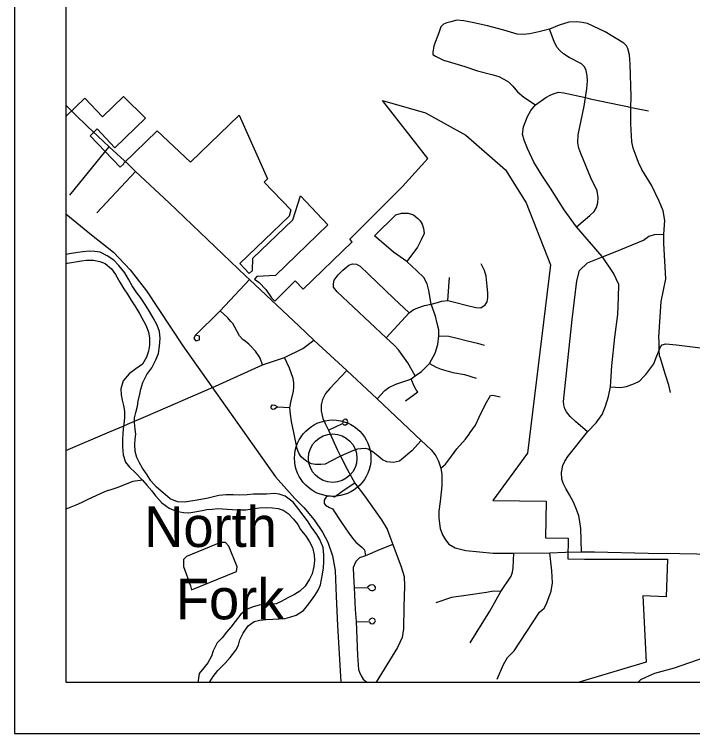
# Model space of a CAD drawing. Extents: x 0 to 34, y 0 to 22.
# Drawn here: x 2 to 3.32, y 14 to 15.4 of the extents above; entities that cross this region are included whole.
import ezdxf

# ---------------------------------------------------------------- set-up
doc = ezdxf.new("R2010")
doc.units = 0
for name, color, linetype in [('GM_X_City_Street', 7, 'Continuous'), ('GM_X_Corporation', 7, 'Continuous'), ('GM_X_County_Road', 7, 'Continuous'), ('GM_X_Major_River', 7, 'Continuous'), ('GM_X_Minor_Lake', 7, 'Continuous'), ('GM_X_Minor_River', 7, 'Continuous'), ('GM_X_Rail_Line', 7, 'Continuous'), ('GM_X_Township_Road', 7, 'Continuous'), ('GM_X_Unincorporated', 7, 'Continuous'), ('GM_X_Unincorporated_Location', 7, 'Continuous'), ('GM_X_Unincorporated_Text', 7, 'Continuous'), ('GM_X_US_Route', 7, 'Continuous'), ('SH_Data', 7, 'Continuous')]:
    doc.layers.add(name, color=color, linetype=linetype)

msp = doc.modelspace()

# ---------------------------------------------------------------- linework, layer by layer
at = {"layer": 'GM_X_City_Street'}
for points in [[(3.2773, 14.6642), (3.2737, 14.6783), (3.2666, 14.7005), (3.2573, 14.731), (3.2556, 14.7353), (3.2553, 14.7463), (3.2547, 14.7637), (3.2541, 14.7722), (3.259, 14.8414), (3.2678, 14.8853), (3.2641, 14.9544), (3.2639, 14.9723), (3.2663, 14.9988), (3.2631, 15.0178), (3.2549, 15.0368), (3.2403, 15.068), (3.2212, 15.0985), (3.2145, 15.1122), (3.2104, 15.124), (3.2041, 15.1396), (3.2019, 15.1522), (3.1999, 15.1871), (3.2001, 15.2192), (3.2003, 15.2398), (3.1984, 15.3032), (3.1974, 15.3214), (3.1937, 15.3336), (3.1915, 15.3389), (3.1862, 15.3446), (3.1501, 15.3661), (3.1153, 15.3823), (3.1051, 15.3846), (3.0949, 15.3858), (3.0794, 15.3852), (3.0604, 15.3796), (3.0418, 15.3717), (3.0206, 15.3666), (3.0031, 15.3625), (2.9906, 15.3614), (2.9789, 15.3619), (2.9524, 15.3693), (2.9207, 15.3778), (2.8942, 15.3837), (2.8749, 15.3876), (2.8609, 15.3888), (2.8492, 15.3858), (2.842, 15.384), (2.8351, 15.381), (2.8298, 15.3761), (2.8259, 15.3643), (2.8166, 15.3394), (2.8143, 15.3261), (2.8146, 15.322), (2.8195, 15.3189)], [(3.0939, 14.9866), (3.1202, 15.0085), (3.1286, 15.0164), (3.1332, 15.0243), (3.1356, 15.0334), (3.1364, 15.044), (3.1342, 15.0569), (3.1223, 15.0821), (3.1025, 15.1296), (3.0985, 15.1399), (3.0966, 15.1501), (3.0975, 15.1661), (3.1093, 15.2218), (3.1116, 15.2382), (3.114, 15.2552), (3.1153, 15.2707), (3.115, 15.281), (3.1132, 15.2912), (3.1098, 15.2981), (3.1038, 15.3038), (3.0796, 15.3161), (3.0691, 15.3234), (3.0623, 15.3291), (3.0556, 15.3364), (3.0503, 15.3478), (3.0418, 15.3717)], [(2.8195, 15.3189), (2.835, 15.3115), (2.8509, 15.3065), (2.8766, 15.2988), (2.9015, 15.2906), (2.9295, 15.2833), (2.9427, 15.2794), (2.9529, 15.2744), (2.9619, 15.269), (2.9702, 15.2606), (2.9792, 15.2495), (2.9916, 15.2392), (3.0146, 15.2243)], [(3.1154, 14.5876), (3.1325, 14.605), (3.144, 14.6215), (3.1508, 14.6374), (3.1565, 14.6561), (3.1601, 14.675), (3.1631, 14.7158), (3.1684, 14.7722), (3.1743, 14.816), (3.1756, 14.8494), (3.1762, 14.8742), (3.1658, 14.8965), (3.1447, 14.9285), (3.1442, 14.9292), (3.0939, 14.9866), (3.07, 15.0198), (3.0434, 15.0621), (3.0269, 15.0876), (3.0112, 15.1127), (2.9985, 15.139), (2.9922, 15.1554), (2.9892, 15.1668), (2.9912, 15.1812), (2.9989, 15.2012), (3.0051, 15.213), (3.0146, 15.2243), (3.0344, 15.2382), (3.0443, 15.2438), (3.0523, 15.2472), (3.0595, 15.2487), (3.0697, 15.2475), (3.1116, 15.2382), (3.1207, 15.2361), (3.1805, 15.2236), (3.1931, 15.2208), (3.2001, 15.2192), (3.2047, 15.2182), (3.2342, 15.2127)], [(3.1154, 14.5876), (3.0924, 14.6075), (3.0818, 14.6175), (3.0744, 14.6262), (3.0714, 14.6323), (3.0695, 14.6404), (3.0691, 14.6466), (3.0859, 14.8066), (3.0945, 14.8814), (3.0997, 14.9017), (3.1154, 14.9168), (3.1447, 14.9285), (3.1693, 14.9383), (3.2248, 14.9607), (3.2351, 14.9683), (3.2468, 14.972), (3.2639, 14.9723)], [(3.1601, 14.675), (3.1799, 14.6742), (3.1913, 14.6759), (3.207, 14.6818), (3.2164, 14.6865), (3.2253, 14.6956), (3.2289, 14.6992), (3.2446, 14.7201), (3.2492, 14.7322), (3.2553, 14.7463), (3.2573, 14.7529), (3.2609, 14.7571), (3.2681, 14.7587), (3.2887, 14.7568), (3.3352, 14.7509)], [(3.2141, 14.1), (3.2194, 14.1051), (3.2293, 14.1099), (3.2464, 14.1174), (3.2851, 14.1278), (3.3427, 14.148), (3.3855, 14.1619), (3.4026, 14.1648), (3.4161, 14.1631), (3.4242, 14.1411)]]:
    msp.add_lwpolyline(points, dxfattribs=at)
at = {"layer": 'GM_X_Corporation'}
for p, q in [((2.1, 15.8164), (2.1, 14.1)), ((2.1, 15.6286), (2.1, 14.9868)), ((2.1, 14.1), (7.1768, 14.1)), ((3.1961, 14.1), (6.9084, 14.1))]:
    msp.add_line(p, q, dxfattribs=at)
for points in [[(3.3801, 16.588), (3.1836, 16.4951), (3.1819, 16.4943), (3.1648, 16.4862), (3.1598, 16.4838), (3.1538, 16.4811), (2.5106, 16.1869), (2.5081, 16.1858), (2.1, 15.9991), (2.1, 14.1), (7.2283, 14.1)], [(2.1, 15.8606), (2.1, 15.2015), (2.1371, 15.2373), (2.1712, 15.2007), (2.2126, 15.2407), (2.2553, 15.1982), (2.1955, 15.1405), (2.1612, 15.1772), (2.1474, 15.1638), (2.206, 15.103), (2.2127, 15.1095), (2.2122, 15.11), (2.2781, 15.1737), (2.343, 15.1129), (2.4376, 15.2042), (2.4928, 15.0801), (2.4864, 15.0737), (2.5382, 15.02), (2.5346, 15.0075), (2.4391, 14.9152), (2.4571, 14.896), (2.4632, 14.9019), (2.4644, 14.9255), (2.5421, 15.0005), (2.5572, 15.047), (2.61, 14.9904), (2.508, 14.8918), (2.472, 14.8899), (2.4671, 14.885), (2.4767, 14.8782), (2.4896, 14.8644), (2.5006, 14.8487), (2.507, 14.842), (2.5467, 14.8817), (2.5622, 14.8656), (2.6576, 14.9577), (2.653, 14.9625), (2.7557, 15.0652), (2.805, 15.1199), (2.7168, 15.2328), (2.7999, 15.2087), (2.8789, 15.1649), (2.9559, 15.098), (2.996, 15.0332), (3.0432, 14.9125), (2.9984, 14.5461), (2.9311, 14.4538), (3.0349, 14.4525), (3.034, 14.3811), (3.078, 14.3806), (3.0775, 14.3403), (3.1099, 14.3395), (3.271, 14.3394), (3.2685, 14.2661), (3.2231, 14.2684), (3.2299, 14.1391), (3.0991, 14.1), (7.0261, 14.1)]]:
    msp.add_lwpolyline(points, dxfattribs=at)
at = {"layer": 'GM_X_County_Road'}
for points in [[(3.1005, 14.4133), (3.0984, 14.4238), (3.0943, 14.4366), (3.0881, 14.4504), (3.0805, 14.465), (3.0735, 14.477), (3.0683, 14.4878), (3.0656, 14.4957), (3.0648, 14.5082), (3.0674, 14.5217), (3.0712, 14.5307), (3.077, 14.5395), (3.1154, 14.5876)], [(3.1035, 14.3542), (3.1025, 14.3995), (3.1007, 14.4124), (3.1005, 14.4133)]]:
    msp.add_lwpolyline(points, dxfattribs=at)
at = {"layer": 'GM_X_Major_River'}
for points in [[(2.2292, 14.8717), (2.2218, 14.8847), (2.2147, 14.8969), (2.2035, 14.9114), (2.1934, 14.9217), (2.1806, 14.9302), (2.1667, 14.9375), (2.1565, 14.9388), (2.1455, 14.9393), (2.133, 14.9382), (2.1235, 14.9368), (2.1114, 14.935), (2.1, 14.9328)], [(2.1, 14.9159), (2.1036, 14.9161), (2.1188, 14.9186), (2.1309, 14.9208), (2.1404, 14.9218), (2.154, 14.9217), (2.1665, 14.9193), (2.1767, 14.9151), (2.1887, 14.9047), (2.1969, 14.894), (2.2051, 14.8791), (2.2133, 14.8658), (2.2204, 14.8558), (2.2278, 14.8429), (2.2345, 14.8326), (2.2434, 14.8177), (2.2568, 14.7937), (2.2612, 14.7815), (2.263, 14.7705), (2.2633, 14.7564), (2.2609, 14.7447), (2.2569, 14.7329), (2.2496, 14.719), (2.2363, 14.7104), (2.2237, 14.7002), (2.2118, 14.6867), (2.2071, 14.6716), (2.2077, 14.6598), (2.2099, 14.6491)], [(2.3799, 14.1), (2.3802, 14.1008), (2.3868, 14.1114), (2.396, 14.1227), (2.4101, 14.137), (2.4197, 14.1479), (2.4309, 14.1622), (2.4359, 14.172), (2.4386, 14.1826), (2.4452, 14.1958), (2.4552, 14.2098), (2.467, 14.218), (2.4777, 14.221), (2.4898, 14.2224), (2.5031, 14.223), (2.5156, 14.2236), (2.5269, 14.2239), (2.5364, 14.2265), (2.5482, 14.2309), (2.5627, 14.2399), (2.5734, 14.2527), (2.585, 14.2689), (2.5911, 14.2795), (2.5958, 14.2897), (2.5978, 14.2999), (2.5994, 14.3105), (2.6014, 14.3226), (2.6023, 14.3352), (2.6021, 14.3484), (2.6007, 14.3621), (2.5945, 14.3781), (2.5885, 14.388), (2.578, 14.4022), (2.5706, 14.414), (2.562, 14.4251), (2.5515, 14.4392), (2.5429, 14.4507), (2.5272, 14.4622), (2.5155, 14.4665), (2.5056, 14.4677), (2.4909, 14.4663), (2.4757, 14.4665), (2.4651, 14.4662), (2.453, 14.4652), (2.4374, 14.4642), (2.4257, 14.4646), (2.4121, 14.4652), (2.398, 14.4634), (2.3874, 14.4608), (2.3772, 14.4586), (2.3661, 14.4565), (2.3559, 14.4547), (2.3434, 14.4525), (2.3309, 14.4507), (2.3172, 14.4512), (2.3029, 14.457), (2.2894, 14.4689), (2.2766, 14.4797), (2.2658, 14.4923), (2.2583, 14.5038), (2.2494, 14.5171), (2.2434, 14.527), (2.2382, 14.5377), (2.2353, 14.5491), (2.2347, 14.5628), (2.2352, 14.5734), (2.2361, 14.5833), (2.2354, 14.5928), (2.234, 14.6057), (2.2341, 14.6151), (2.2365, 14.625), (2.2393, 14.6375), (2.2409, 14.647), (2.2444, 14.661), (2.2461, 14.6704), (2.25, 14.6837), (2.2577, 14.6995), (2.2673, 14.712), (2.2754, 14.7275), (2.2805, 14.7403), (2.2825, 14.7543), (2.2838, 14.7691), (2.2825, 14.7828), (2.2777, 14.7954), (2.2702, 14.8095), (2.2632, 14.8221), (2.2546, 14.8354), (2.2453, 14.8488), (2.2386, 14.8583), (2.2292, 14.8717)], [(2.2099, 14.6491), (2.2124, 14.6389), (2.2146, 14.6275), (2.2144, 14.6149), (2.2128, 14.6028), (2.2115, 14.5933), (2.2111, 14.5839), (2.2106, 14.5732), (2.2104, 14.5585), (2.2114, 14.5429), (2.2162, 14.5284), (2.224, 14.5189), (2.2353, 14.5085), (2.2495, 14.4936), (2.2577, 14.4836), (2.2675, 14.4726), (2.2749, 14.463), (2.2873, 14.4496), (2.3012, 14.4389), (2.3148, 14.433), (2.3291, 14.4302), (2.3394, 14.4298), (2.3511, 14.4316), (2.3652, 14.4345), (2.3746, 14.4363), (2.3849, 14.4373), (2.3963, 14.438), (2.414, 14.4371), (2.4243, 14.4362), (2.4413, 14.4357), (2.4508, 14.436), (2.4629, 14.4374), (2.4762, 14.4395), (2.491, 14.4401), (2.5027, 14.4397), (2.5133, 14.4384), (2.5231, 14.4349), (2.5329, 14.4288), (2.543, 14.4173), (2.552, 14.407), (2.5568, 14.3974), (2.568, 14.384), (2.5747, 14.3737), (2.5803, 14.3623), (2.5835, 14.3482), (2.5842, 14.3368), (2.5829, 14.3255), (2.5794, 14.3111), (2.5747, 14.3005), (2.5662, 14.2873), (2.5559, 14.2775), (2.5452, 14.2708), (2.5334, 14.2648), (2.5193, 14.2574), (2.5094, 14.2529), (2.4985, 14.2523), (2.4859, 14.2516), (2.4765, 14.2502), (2.4647, 14.2469), (2.4529, 14.242), (2.4407, 14.2323), (2.4295, 14.2184), (2.4215, 14.2074), (2.4127, 14.1976), (2.4042, 14.1863), (2.395, 14.1766), (2.3869, 14.1615), (2.3834, 14.1509), (2.3764, 14.1377), (2.3688, 14.1279), (2.3599, 14.1173), (2.3579, 14.1033), (2.3579, 14.1)]]:
    msp.add_lwpolyline(points, dxfattribs=at)
at = {"layer": 'GM_X_Minor_Lake'}
for points in [[(2.3428, 14.2878), (2.345, 14.2798), (2.4325, 14.3158), (2.4333, 14.3246), (2.4175, 14.3649), (2.4111, 14.3718), (2.4009, 14.3719), (2.3347, 14.3448), (2.3293, 14.3392), (2.3292, 14.3255)], [(2.3292, 14.3255), (2.3428, 14.2878)]]:
    msp.add_lwpolyline(points, dxfattribs=at)
at = {"layer": 'GM_X_Minor_River'}
msp.add_lwpolyline([(2.2495, 14.4936), (2.2305, 14.4911), (2.2153, 14.4848), (2.2016, 14.4792), (2.1899, 14.4755), (2.1788, 14.4718), (2.1682, 14.4678), (2.1415, 14.4551), (2.1297, 14.4495), (2.1199, 14.4451), (2.11, 14.441), (2.1, 14.4369)], dxfattribs=at)
at = {"layer": 'GM_X_Rail_Line'}
msp.add_line((2.5504, 14.1011), (2.5504, 14.1), dxfattribs=at)
msp.add_lwpolyline([(2.1, 15.0118), (2.1504, 14.9712), (2.1926, 14.9374), (2.2255, 14.9027), (2.2573, 14.8622), (2.3278, 14.7552), (2.508, 14.4997), (2.5461, 14.4575), (2.5632, 14.4404), (2.5832, 14.4164), (2.5995, 14.392), (2.6102, 14.373), (2.6189, 14.3464), (2.6245, 14.3177), (2.6262, 14.2672), (2.6289, 14.2104), (2.6355, 14.1)], dxfattribs=at)
at = {"layer": 'GM_X_Township_Road'}
for p, q in [((2.1783, 15.1348), (2.1847, 15.1427)), ((2.1081, 15.0481), (2.1783, 15.1348)), ((2.1604, 15.014), (2.2358, 15.0947)), ((2.8436, 14.8433), (2.847, 14.888)), ((2.4826, 14.7182), (2.5258, 14.7321)), ((2.2554, 14.6176), (2.3871, 14.6748)), ((2.185, 14.5873), (2.2115, 14.5986)), ((2.1, 14.551), (2.185, 14.5873)), ((2.9718, 14.1), (2.9718, 14.1))]:
    msp.add_line(p, q, dxfattribs=at)
for points in [[(2.7012, 14.969), (2.7425, 15.01), (2.7532, 15.013), (2.7665, 15.0135), (2.7766, 15.01), (2.7852, 15.0031), (2.7899, 14.9985), (2.7934, 14.9916), (2.7965, 14.9837), (2.7973, 14.9738), (2.7919, 14.9616), (2.7848, 14.9473), (2.7639, 14.919)], [(2.8112, 14.8359), (2.8066, 14.8627), (2.8032, 14.8754), (2.7972, 14.888), (2.7835, 14.9011), (2.7639, 14.919), (2.7377, 14.9377), (2.7012, 14.969)], [(2.78, 14.6963), (2.766, 14.7216), (2.7563, 14.7355), (2.7477, 14.7475), (2.7394, 14.7563), (2.7239, 14.7707), (2.628, 14.8599), (2.6212, 14.8694), (2.6208, 14.876), (2.6223, 14.8826), (2.6303, 14.8933), (2.639, 14.9024), (2.6512, 14.9119), (2.6578, 14.9144), (2.6656, 14.914), (2.6728, 14.9099), (2.7383, 14.8471), (2.7682, 14.8192)], [(2.8112, 14.8359), (2.8234, 14.8392), (2.8314, 14.8418), (2.8436, 14.8433), (2.8567, 14.8398), (2.882, 14.8336), (2.8979, 14.8294), (2.9077, 14.829), (2.9164, 14.8346), (2.9203, 14.8404), (2.9214, 14.8483), (2.9212, 14.8578), (2.9205, 14.8711), (2.918, 14.8907), (2.9151, 14.9017), (2.9087, 14.9144)], [(2.4578, 14.884), (2.4006, 14.8234), (2.3516, 14.7751), (2.3494, 14.7692), (2.3531, 14.7648), (2.3605, 14.767), (2.3605, 14.7737), (2.3527, 14.7758)], [(2.7239, 14.7707), (2.7682, 14.8192), (2.7761, 14.8254), (2.785, 14.8293), (2.798, 14.8334), (2.8112, 14.8359)], [(2.7699, 14.6897), (2.7725, 14.6906), (2.78, 14.6963), (2.7927, 14.7048), (2.808, 14.7208), (2.8189, 14.7408), (2.824, 14.7576), (2.8259, 14.7742), (2.8259, 14.7859), (2.8232, 14.7985), (2.8194, 14.813), (2.8112, 14.8359)], [(2.4561, 14.7581), (2.4489, 14.7644), (2.4447, 14.7676), (2.4381, 14.7748), (2.4292, 14.7911), (2.4249, 14.7986), (2.4216, 14.8024), (2.4156, 14.8098), (2.4006, 14.8234)], [(2.8259, 14.7742), (2.8456, 14.7739), (2.8619, 14.7702), (2.8822, 14.7648), (2.9016, 14.76), (2.9145, 14.7563)], [(2.5258, 14.7321), (2.5613, 14.75), (2.5826, 14.7661)], [(2.4826, 14.7182), (2.4782, 14.7311), (2.4765, 14.7341), (2.469, 14.7449), (2.4597, 14.7549), (2.4561, 14.7581)], [(2.7915, 14.5706), (2.7734, 14.5508), (2.7533, 14.5334), (2.7494, 14.5306), (2.7379, 14.5278), (2.7252, 14.5293), (2.7166, 14.533), (2.7079, 14.5399), (2.6986, 14.5479), (2.6886, 14.5538), (2.6833, 14.5549), (2.6746, 14.5547), (2.6677, 14.5541), (2.6601, 14.5515), (2.6347, 14.5399), (2.6162, 14.5303), (2.6049, 14.5248), (2.5967, 14.5239), (2.5861, 14.5239), (2.578, 14.5253), (2.5693, 14.5295), (2.5633, 14.5343), (2.5585, 14.5391), (2.5537, 14.546), (2.5506, 14.5543), (2.5442, 14.5861), (2.5394, 14.6074), (2.5372, 14.6222), (2.5361, 14.634), (2.5386, 14.6479), (2.5432, 14.6668), (2.5442, 14.6746), (2.544, 14.6828), (2.5427, 14.6912), (2.5354, 14.7116), (2.5258, 14.7321)], [(2.3871, 14.6748), (2.3915, 14.6767), (2.4826, 14.7182)], [(2.808, 14.7208), (2.8207, 14.7133), (2.8304, 14.7093), (2.8532, 14.7033), (2.8758, 14.6992), (2.8987, 14.692)], [(2.6468, 14.7072), (2.6138, 14.672), (2.6058, 14.6625), (2.5999, 14.6507), (2.5974, 14.6403), (2.5971, 14.6283), (2.6003, 14.6138), (2.6046, 14.604), (2.6111, 14.591), (2.628, 14.553), (2.6347, 14.5399), (2.6478, 14.5152), (2.6624, 14.4875), (2.6817, 14.463), (2.7, 14.4362), (2.7146, 14.4161), (2.7254, 14.3978), (2.7305, 14.3837), (2.7363, 14.3682), (2.7531, 14.3248), (2.7585, 14.3056), (2.7594, 14.2871), (2.7579, 14.2468), (2.7576, 14.2038), (2.7547, 14.1874), (2.7456, 14.1675), (2.7044, 14.1)], [(2.7061, 14.6519), (2.7208, 14.6679), (2.7286, 14.6739), (2.7423, 14.6801), (2.7558, 14.6848), (2.7699, 14.6897)], [(2.7615, 14.6479), (2.7853, 14.6654), (2.7823, 14.6696), (2.7773, 14.6781), (2.7725, 14.6906)], [(2.8849, 14.5828), (2.8872, 14.586), (2.8974, 14.6003), (2.9048, 14.6162), (2.9171, 14.6412), (2.927, 14.6586), (2.9313, 14.6589), (2.9454, 14.6559)], [(2.5361, 14.634), (2.5112, 14.6354), (2.5065, 14.6315), (2.5022, 14.6313), (2.5, 14.6335), (2.5, 14.637), (2.5027, 14.6401), (2.5068, 14.6398), (2.5114, 14.6367)], [(2.2115, 14.5986), (2.2203, 14.6024), (2.2554, 14.6176)], [(2.6111, 14.591), (2.6385, 14.6041), (2.6415, 14.6015), (2.6452, 14.6009), (2.648, 14.6032), (2.6489, 14.6069), (2.6477, 14.61), (2.6452, 14.612), (2.6418, 14.6116), (2.6388, 14.6085), (2.6392, 14.6052)], [(2.8302, 14.5166), (2.8392, 14.5247), (2.8507, 14.5401), (2.8609, 14.5546), (2.878, 14.5733), (2.8849, 14.5828)], [(2.6624, 14.4875), (2.6437, 14.4752), (2.6232, 14.4605), (2.6153, 14.462), (2.6108, 14.4623), (2.607, 14.4607), (2.6032, 14.4547), (2.6032, 14.4482), (2.6056, 14.4446), (2.6135, 14.4401), (2.6191, 14.4376), (2.637, 14.411), (2.6508, 14.3904), (2.658, 14.3803), (2.6645, 14.3729), (2.6764, 14.3629), (2.6815, 14.3577), (2.6833, 14.3463)], [(2.7363, 14.3682), (2.7122, 14.3582), (2.6833, 14.3463), (2.672, 14.3424), (2.6644, 14.3352), (2.6597, 14.3236), (2.6601, 14.307), (2.6611, 14.2842), (2.6633, 14.2416), (2.6653, 14.2185), (2.668, 14.1524), (2.6697, 14.1248), (2.6717, 14.1198), (2.6748, 14.1124), (2.6791, 14.106), (2.686, 14.1)], [(2.8871, 14.1765), (2.9253, 14.2384), (2.9465, 14.2765), (2.9666, 14.3063), (2.9697, 14.3146), (2.9705, 14.3227), (2.9722, 14.3513)], [(2.9395, 14.1061), (2.9518, 14.1348), (2.9599, 14.1485), (2.9726, 14.1612), (3.0221, 14.2363), (3.0313, 14.2444), (3.0353, 14.2515), (3.0405, 14.2649), (3.0451, 14.2773), (3.0474, 14.2933), (3.0459, 14.3167), (3.0421, 14.3517)], [(2.6611, 14.2842), (2.6882, 14.284), (2.6922, 14.2794), (2.6953, 14.2787), (2.6982, 14.2789), (2.7011, 14.2802), (2.7023, 14.2809), (2.703, 14.2833), (2.7026, 14.2849), (2.7017, 14.2874), (2.6995, 14.2892), (2.6969, 14.2899), (2.6928, 14.2892), (2.6872, 14.2849)], [(2.9465, 14.2765), (2.9328, 14.2772), (2.9186, 14.2748), (2.8834, 14.2696), (2.8509, 14.265), (2.8205, 14.2548)], [(2.6653, 14.2185), (2.6905, 14.2179), (2.6929, 14.2146), (2.6966, 14.2137), (2.6999, 14.2146), (2.7017, 14.2171), (2.7026, 14.2199), (2.7017, 14.222), (2.7001, 14.2238), (2.6969, 14.2249), (2.6932, 14.2234), (2.6901, 14.2203)]]:
    msp.add_lwpolyline(points, dxfattribs=at)
at = {"layer": 'GM_X_Unincorporated'}
for radius in [0.0744, 0.0472]:
    msp.add_circle((2.6196, 14.5363), radius, dxfattribs=at)
at = {"layer": 'GM_X_Unincorporated_Location'}
msp.add_line((2.6196, 14.5363), (2.6196, 14.5363), dxfattribs=at)
at = {"layer": 'GM_X_US_Route'}
for p, q in [((2.1, 15.2234), (2.1184, 15.2056)), ((2.5535, 14.7938), (2.5826, 14.7661))]:
    msp.add_line(p, q, dxfattribs=at)
for points in [[(2.1184, 15.2056), (2.1426, 15.1823), (2.1626, 15.1635)], [(2.1626, 15.1635), (2.1847, 15.1427), (2.2212, 15.1084)], [(2.2212, 15.1084), (2.2358, 15.0947), (2.3011, 15.0335), (2.4506, 14.8909)], [(2.4506, 14.8909), (2.4578, 14.884), (2.5433, 14.8035), (2.5535, 14.7938)], [(2.5826, 14.7661), (2.6468, 14.7072), (2.7061, 14.6519), (2.7915, 14.5706), (2.8111, 14.5525), (2.8186, 14.5432)], [(2.8186, 14.5432), (2.8205, 14.5409), (2.8257, 14.5302), (2.8302, 14.5166), (2.8317, 14.5047), (2.8319, 14.4826), (2.8289, 14.4519), (2.8264, 14.4334), (2.826, 14.4194), (2.8285, 14.3991), (2.8332, 14.3868), (2.8391, 14.3771), (2.8459, 14.3691), (2.8577, 14.3619), (2.8784, 14.3564), (2.9317, 14.3513), (2.9722, 14.3513), (3.0421, 14.3517), (3.0728, 14.353)], [(3.0728, 14.353), (3.1035, 14.3542), (3.1134, 14.3542)], [(3.1134, 14.3542), (3.1293, 14.3542), (3.2339, 14.3513), (3.2952, 14.3504)], [(3.2952, 14.3504), (3.3283, 14.35), (3.3725, 14.3464), (3.3843, 14.3446), (3.4236, 14.3389), (3.4266, 14.3387)]]:
    msp.add_lwpolyline(points, dxfattribs=at)
at = {"layer": 'SH_Data'}
for p, q in [((2, 21), (2, 14)), ((2.1, 20.9), (2.1, 14.1)), ((2.1, 14.1), (8.9, 14.1)), ((2.1, 14.1), (2.1, 14.1)), ((2, 14), (9, 14))]:
    msp.add_line(p, q, dxfattribs=at)

# ---------------------------------------------------------------- texts
at = {"layer": 'GM_X_Unincorporated_Text'}
for s, p in [('North', (2.2526, 14.3633)), ('Fork', (2.3143, 14.2225))]:
    msp.add_text(s, height=0.07898, rotation=0, dxfattribs=at).set_placement(p)

doc.saveas('drawing.dxf')
